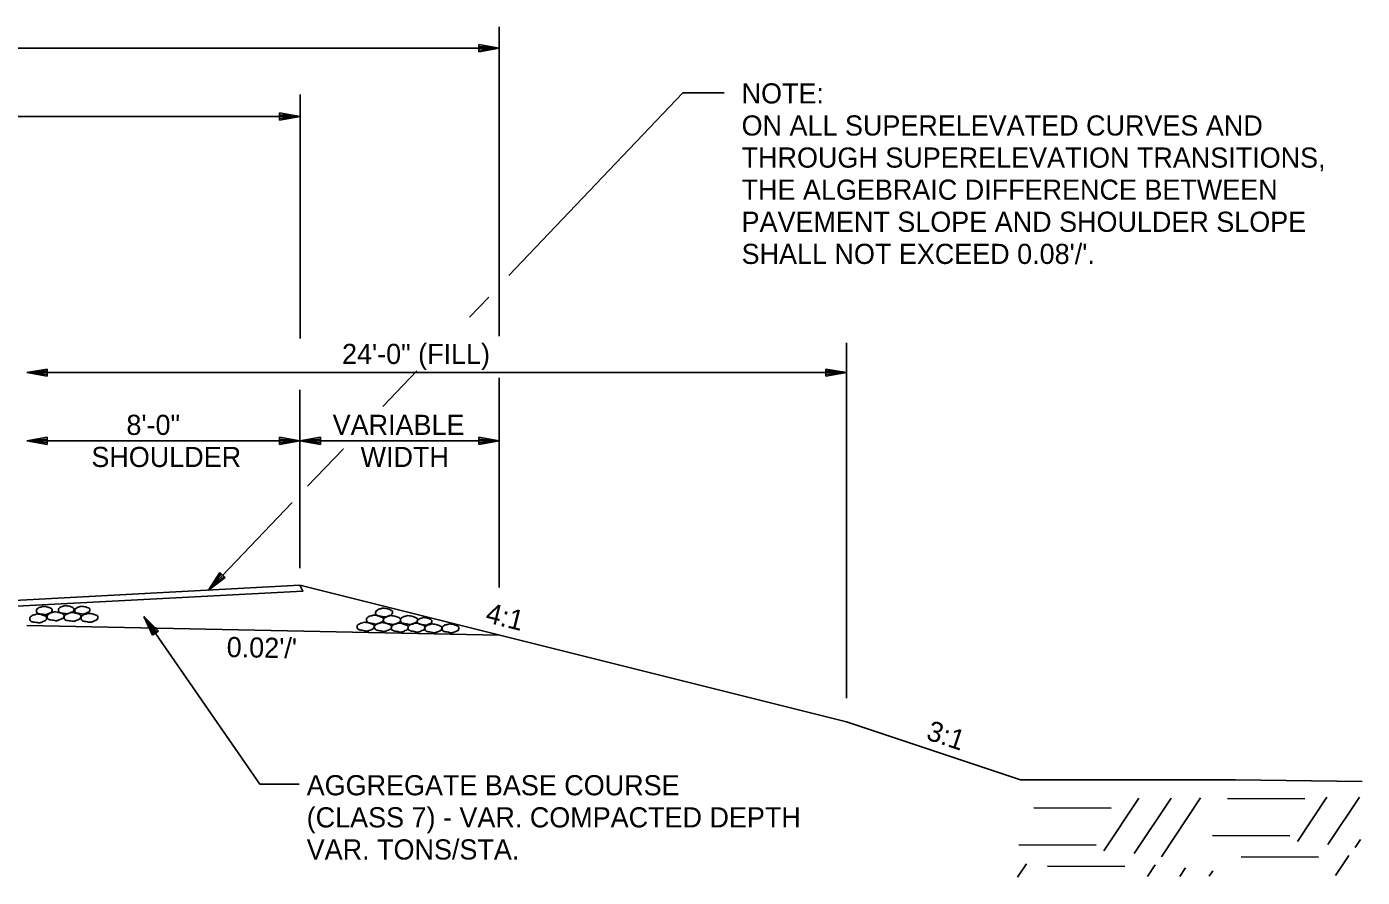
# Model space of a CAD drawing. Extents: x 1398183 to 1398373, y 1967240 to 1968889.
# Drawn here: x 1398260.45 to 1398299.55, y 1968086.97 to 1968111.88 of the extents above; entities that cross this region are included whole.
import ezdxf

# ---------------------------------------------------------------- set-up
doc = ezdxf.new("R2010")
doc.units = 0
for name, color, linetype in [('1', 7, 'Continuous'), ('10', 7, 'Continuous'), ('19', 7, 'Continuous'), ('42', 7, 'Continuous'), ('9', 7, 'Continuous'), ('Level 1', 7, 'Continuous')]:
    doc.layers.add(name, color=color, linetype=linetype)

# ---------------------------------------------------------------- blocks, each defined once
blk = doc.blocks.new('ROCKS')
at = {"layer": '1'}
blk.add_spline([(0.013, 0.06), (0.053, 0.053), (0.107, 0.033), (0.133, 0.013), (0.133, -0.007), (0.12, -0.033), (0.107, -0.04), (0.073, -0.053), (0.033, -0.067), (0.013, -0.067), (-0.02, -0.06), (-0.06, -0.053), (-0.087, -0.047), (-0.113, -0.02), (-0.113, -0.007), (-0.107, 0.02), (-0.087, 0.033), (-0.067, 0.047), (-0.033, 0.053), (-0.02, 0.06), (0.013, 0.06)], degree=3, dxfattribs=at)

msp = doc.modelspace()

# ---------------------------------------------------------------- linework, layer by layer
at = {"layer": '19'}
for p, q in [((1398274.281, 1968102.818), (1398274.281, 1968111.876)), ((1398273.681, 1968111.353), (1398273.681, 1968111.143)), ((1398274.281, 1968111.248), (1398273.681, 1968111.353)), ((1398274.121, 1968111.263), (1398273.681, 1968111.298)), ((1398212.441, 1968111.247), (1398274.281, 1968111.247)), ((1398273.681, 1968111.143), (1398274.281, 1968111.248)), ((1398273.681, 1968111.193), (1398274.121, 1968111.233)), ((1398268.448, 1968102.748), (1398268.448, 1968109.894)), ((1398267.848, 1968109.352), (1398267.848, 1968109.142)), ((1398268.448, 1968109.247), (1398267.848, 1968109.352)), ((1398268.288, 1968109.262), (1398267.848, 1968109.297)), ((1398268.448, 1968109.247), (1398218.448, 1968109.247)), ((1398267.848, 1968109.142), (1398268.448, 1968109.247)), ((1398267.848, 1968109.192), (1398268.288, 1968109.232)), ((1398284.446, 1968092.215), (1398284.446, 1968102.623)), ((1398261.046, 1968101.852), (1398260.446, 1968101.747)), ((1398284.446, 1968101.747), (1398260.446, 1968101.747)), ((1398260.446, 1968101.747), (1398261.046, 1968101.642)), ((1398261.046, 1968101.797), (1398260.606, 1968101.762)), ((1398260.606, 1968101.732), (1398261.046, 1968101.692)), ((1398261.046, 1968101.642), (1398261.046, 1968101.852)), ((1398274.28, 1968095.45), (1398274.28, 1968101.597)), ((1398283.846, 1968101.852), (1398283.846, 1968101.642)), ((1398284.446, 1968101.747), (1398283.846, 1968101.852)), ((1398284.286, 1968101.762), (1398283.846, 1968101.797)), ((1398283.846, 1968101.642), (1398284.446, 1968101.747)), ((1398283.846, 1968101.692), (1398284.286, 1968101.732)), ((1398268.446, 1968096.02), (1398268.446, 1968101.239)), ((1398261.046, 1968099.852), (1398260.446, 1968099.747)), ((1398260.446, 1968099.747), (1398261.046, 1968099.642)), ((1398260.446, 1968099.747), (1398268.446, 1968099.747)), ((1398261.046, 1968099.797), (1398260.606, 1968099.762)), ((1398260.606, 1968099.732), (1398261.046, 1968099.692)), ((1398261.046, 1968099.642), (1398261.046, 1968099.852)), ((1398267.846, 1968099.852), (1398267.846, 1968099.642)), ((1398268.446, 1968099.747), (1398267.846, 1968099.852)), ((1398268.286, 1968099.762), (1398267.846, 1968099.797)), ((1398267.846, 1968099.642), (1398268.446, 1968099.747)), ((1398267.846, 1968099.692), (1398268.286, 1968099.732)), ((1398269.046, 1968099.852), (1398268.446, 1968099.747)), ((1398268.446, 1968099.747), (1398274.28, 1968099.747)), ((1398268.446, 1968099.747), (1398269.046, 1968099.642)), ((1398269.046, 1968099.797), (1398268.606, 1968099.762)), ((1398268.606, 1968099.732), (1398269.046, 1968099.692)), ((1398269.046, 1968099.642), (1398269.046, 1968099.852)), ((1398273.68, 1968099.853), (1398273.68, 1968099.643)), ((1398274.28, 1968099.748), (1398273.68, 1968099.853)), ((1398274.12, 1968099.763), (1398273.68, 1968099.798)), ((1398273.68, 1968099.643), (1398274.28, 1968099.748)), ((1398273.68, 1968099.693), (1398274.12, 1968099.733)), ((1398265.769, 1968095.378), (1398266.1, 1968095.889)), ((1398266.252, 1968095.745), (1398265.769, 1968095.378)), ((1398265.868, 1968095.502), (1398266.137, 1968095.85)), ((1398266.216, 1968095.779), (1398265.889, 1968095.483)), ((1398266.1, 1968095.889), (1398266.252, 1968095.745)), ((1398268.446, 1968095.52), (1398284.446, 1968091.52)), ((1398268.446, 1968095.52), (1398268.531, 1968095.35)), ((1398264.127, 1968094.057), (1398263.874, 1968094.609)), ((1398263.874, 1968094.609), (1398264.3, 1968094.174)), ((1398267.273, 1968089.691), (1398263.874, 1968094.609)), ((1398264.167, 1968094.085), (1398263.951, 1968094.469)), ((1398263.974, 1968094.485), (1398264.254, 1968094.146)), ((1398260.446, 1968094.338), (1398274.28, 1968094.061)), ((1398264.3, 1968094.174), (1398264.127, 1968094.057)), ((1398284.446, 1968091.52), (1398289.546, 1968089.819)), ((1398268.423, 1968089.691), (1398267.273, 1968089.691))]:
    msp.add_line(p, q, dxfattribs=at)
for points in [[(1398280.867, 1968109.936), (1398279.658, 1968109.936), (1398274.565, 1968104.591)], [(1398273.973, 1968103.96), (1398273.411, 1968103.373)], [(1398271.865, 1968101.798), (1398270.872, 1968100.753)], [(1398269.712, 1968099.507), (1398269.712, 1968099.507), (1398268.666, 1968098.421)], [(1398268.209, 1968097.933), (1398268.209, 1968097.933), (1398265.769, 1968095.378)], [(1398268.446, 1968095.52), (1398260.446, 1968095.096), (1398248.446, 1968094.46), (1398236.446, 1968093.824), (1398224.446, 1968093.188), (1398218.446, 1968092.87)]]:
    msp.add_lwpolyline(points, dxfattribs=at)
msp.add_lwpolyline([(1398218.361, 1968092.7), (1398224.361, 1968093.018), (1398248.436, 1968094.287), (1398260.531, 1968094.925), (1398268.531, 1968095.35), (1398268.446, 1968095.52), (1398260.446, 1968095.096), (1398248.446, 1968094.46), (1398224.446, 1968093.188), (1398218.446, 1968092.87)], close=True, dxfattribs=at)
at = {"layer": '42'}
msp.add_lwpolyline([(1398289.546, 1968089.819), (1398295.832, 1968089.819), (1398299.548, 1968089.769)], dxfattribs=at)
at = {"layer": '9'}
for p, q in [((1398292.194, 1968088.991), (1398289.932, 1968088.997)), ((1398293.001, 1968089.282), (1398291.978, 1968087.747)), ((1398293.953, 1968089.287), (1398292.869, 1968087.66)), ((1398294.813, 1968089.292), (1398293.666, 1968087.571)), ((1398297.866, 1968089.264), (1398295.604, 1968089.27)), ((1398298.511, 1968089.312), (1398297.65, 1968088.02)), ((1398299.464, 1968089.318), (1398298.54, 1968087.932)), ((1398297.427, 1968088.186), (1398295.165, 1968088.192)), ((1398291.755, 1968087.913), (1398289.493, 1968087.919)), ((1398299.492, 1968088.075), (1398299.338, 1968087.844)), ((1398298.265, 1968087.56), (1398296.003, 1968087.566)), ((1398299.154, 1968087.602), (1398298.766, 1968087.019)), ((1398289.718, 1968087.364), (1398289.454, 1968086.967)), ((1398292.593, 1968087.287), (1398290.331, 1968087.293)), ((1398293.482, 1968087.329), (1398293.255, 1968086.989)), ((1398294.373, 1968087.241), (1398294.208, 1968086.994)), ((1398295.171, 1968087.153), (1398295.068, 1968086.999))]:
    msp.add_line(p, q, dxfattribs=at)

# ---------------------------------------------------------------- block references
at = {"layer": 'Level 1'}
for p, xscale, yscale, rotation in [((1398260.941, 1968094.784), 1.8866375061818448, 1.886637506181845, 1.8263814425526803), ((1398261.582, 1968094.808), 1.851115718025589, 1.851115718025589, 1.8263814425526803), ((1398262.057, 1968094.795), 1.773922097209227, 1.773922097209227, 1.8263814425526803), ((1398270.889, 1968094.727), 2.011654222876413, 2.0116542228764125, -0.17361855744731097), ((1398260.762, 1968094.553), 2.011654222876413, 2.011654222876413, 1.8263814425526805), ((1398261.27, 1968094.616), 2.011654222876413, 2.011654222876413, 1.8263814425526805), ((1398261.765, 1968094.597), 2.011654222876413, 2.011654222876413, 1.8263814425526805), ((1398262.262, 1968094.572), 2.011654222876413, 2.011654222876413, 1.8263814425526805), ((1398270.35, 1968094.312), 2.011654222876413, 2.0116542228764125, -0.17361855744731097), ((1398270.35, 1968094.312), 2.011654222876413, 2.0116542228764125, -0.17361855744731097), ((1398270.62, 1968094.519), 2.011654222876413, 2.0116542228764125, -0.17361855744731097), ((1398271.121, 1968094.507), 2.011654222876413, 2.0116542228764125, -0.17361855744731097), ((1398271.616, 1968094.507), 2.011654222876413, 2.0116542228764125, -0.17361855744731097), ((1398272.078, 1968094.468), 1.7335100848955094, 1.7335100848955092, -0.173618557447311), ((1398270.855, 1968094.302), 2.011654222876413, 2.0116542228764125, -0.17361855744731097), ((1398270.855, 1968094.302), 2.011654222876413, 2.0116542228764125, -0.17361855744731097), ((1398271.347, 1968094.284), 2.011654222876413, 2.0116542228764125, -0.17361855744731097), ((1398271.347, 1968094.284), 2.011654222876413, 2.0116542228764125, -0.17361855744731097), ((1398271.837, 1968094.284), 2.011654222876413, 2.0116542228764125, -0.17361855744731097), ((1398271.837, 1968094.284), 2.011654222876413, 2.0116542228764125, -0.17361855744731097), ((1398272.33, 1968094.264), 2.011654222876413, 2.0116542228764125, -0.17361855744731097), ((1398272.33, 1968094.264), 2.011654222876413, 2.0116542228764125, -0.17361855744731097), ((1398272.832, 1968094.264), 2.011654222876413, 2.0116542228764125, -0.17361855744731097), ((1398272.832, 1968094.264), 2.011654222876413, 2.0116542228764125, -0.17361855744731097)]:
    msp.add_blockref('ROCKS', p, dxfattribs=dict(at, xscale=xscale, yscale=yscale, rotation=rotation))

# ---------------------------------------------------------------- texts
at = {"layer": '10'}
for s, height, p in [('24\'-0" (FILL)', 0.59001, (1398269.677, 1968101.999)), ('8\'-0"', 0.59, (1398263.365, 1968099.922)), ('VARIABLE', 0.59, (1398269.403, 1968099.922)), ('SHOULDER', 0.59, (1398262.339, 1968098.982)), ('WIDTH', 0.59, (1398270.221, 1968098.982))]:
    msp.add_text(s, height=height, dxfattribs=at).set_placement(p)
for s, rotation, p in [('4:1', 345.9638, (1398273.848, 1968094.445)), ('3:1', 341.5868, (1398286.75, 1968091.016))]:
    msp.add_text(s, height=0.59, rotation=rotation, dxfattribs=at).set_placement(p)
at = {"layer": '19'}
for s, height, p in [('NOTE:', 0.59, (1398281.376, 1968109.629)), ('ON ALL SUPERELEVATED CURVES AND', 0.59001, (1398281.376, 1968108.689)), ('THROUGH SUPERELEVATION TRANSITIONS,', 0.59001, (1398281.376, 1968107.749)), ('THE ALGEBRAIC DIFFERENCE BETWEEN', 0.59001, (1398281.376, 1968106.809)), ('PAVEMENT SLOPE AND SHOULDER SLOPE', 0.59001, (1398281.376, 1968105.869)), ("SHALL NOT EXCEED 0.08'/'.", 0.59001, (1398281.376, 1968104.929))]:
    msp.add_text(s, height=height, dxfattribs=at).set_placement(p)
for s, height, rotation, p in [("0.02'/'", 0.59, 358.8542, (1398266.296, 1968093.419)), ('AGGREGATE BASE COURSE', 0.59001, 360, (1398268.643, 1968089.368)), ('(CLASS 7) - VAR. COMPACTED DEPTH', 0.59001, 360, (1398268.643, 1968088.428)), ('VAR. TONS/STA.', 0.59001, 360, (1398268.643, 1968087.488))]:
    msp.add_text(s, height=height, rotation=rotation, dxfattribs=at).set_placement(p)

doc.saveas('drawing.dxf')
